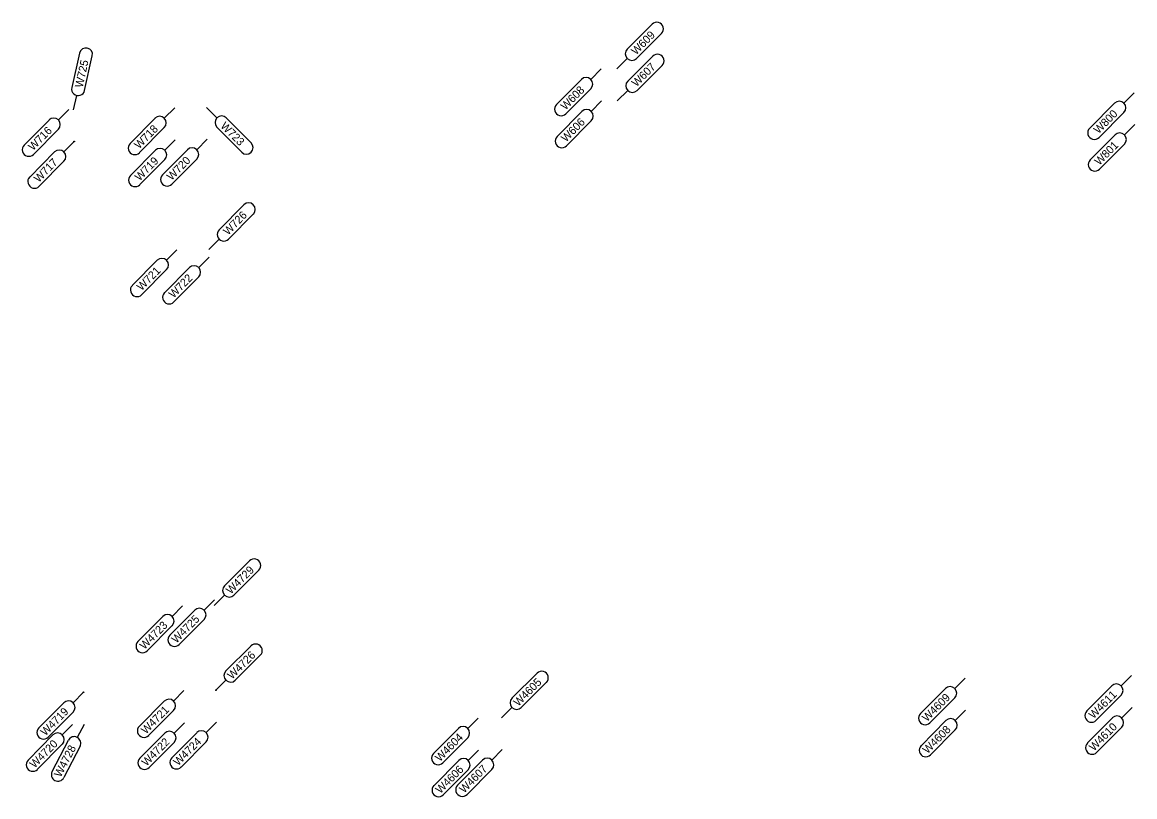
# Model space of a CAD drawing. Extents: x 12479652 to 12487250, y 9842710 to 9846560.
# Drawn here: x 12480939.8 to 12481113.6, y 9842722.3 to 9842843.2 of the extents above; entities that cross this region are included whole.
import ezdxf

# ---------------------------------------------------------------- set-up
doc = ezdxf.new("R2010")
doc.units = 0
doc.layers.add('_CIVIL_CONSTRUCTION', color=7, linetype='Continuous')
doc.layers.add('TextAlignmentLrg', color=7, linetype='Continuous')

msp = doc.modelspace()

# ---------------------------------------------------------------- linework, layer by layer
at = {"layer": '_CIVIL_CONSTRUCTION'}
for p, q in [((12481038.26, 9842842.95), (12481034.35, 9842839.06)), ((12481035.79, 9842837.6), (12481039.71, 9842841.49)), ((12480948.77, 9842838.43), (12480947.57, 9842833.04)), ((12480949.57, 9842832.6), (12480950.77, 9842837.99)), ((12481032.71, 9842835.99), (12481034.34, 9842837.61)), ((12481038.34, 9842837.95), (12481034.43, 9842834.06)), ((12481030.26, 9842835.96), (12481028.64, 9842834.32)), ((12481035.87, 9842832.6), (12481039.79, 9842836.49)), ((12481023.3, 9842830.41), (12481027.19, 9842834.32)), ((12480947.85, 9842829.57), (12480948.35, 9842831.82)), ((12481028.65, 9842832.87), (12481024.76, 9842828.96)), ((12481032.79, 9842830.99), (12481034.42, 9842832.61)), ((12481113.55, 9842832.24), (12481111.93, 9842830.61)), ((12481030.34, 9842830.96), (12481028.72, 9842829.33)), ((12481106.59, 9842826.7), (12481110.48, 9842830.61)), ((12480947.09, 9842829.62), (12480945.47, 9842827.99)), ((12480956.68, 9842824.34), (12480960.57, 9842828.25)), ((12480963.64, 9842829.88), (12480962.02, 9842828.25)), ((12480968.62, 9842829.95), (12480970.25, 9842828.32)), ((12480975.59, 9842824.4), (12480971.7, 9842828.32)), ((12481023.38, 9842825.41), (12481027.27, 9842829.32)), ((12481111.94, 9842829.16), (12481108.05, 9842825.25)), ((12480940.12, 9842824.07), (12480944.01, 9842827.98)), ((12480945.47, 9842826.54), (12480941.58, 9842822.62)), ((12480962.02, 9842826.8), (12480958.13, 9842822.89)), ((12480970.24, 9842826.87), (12480974.13, 9842822.96)), ((12481028.73, 9842827.87), (12481024.84, 9842823.96)), ((12481113.63, 9842827.29), (12481112.01, 9842825.66)), ((12480963.72, 9842824.88), (12480962.1, 9842823.25)), ((12480968.72, 9842824.97), (12480967.1, 9842823.33)), ((12481106.67, 9842821.75), (12481110.56, 9842825.66)), ((12480947.95, 9842824.63), (12480946.33, 9842823)), ((12480956.76, 9842819.34), (12480960.65, 9842823.25)), ((12480961.76, 9842819.42), (12480965.65, 9842823.33)), ((12481112.02, 9842824.21), (12481108.13, 9842820.3)), ((12480940.99, 9842819.08), (12480944.88, 9842823)), ((12480946.34, 9842821.55), (12480942.45, 9842817.64)), ((12480962.1, 9842821.8), (12480958.21, 9842817.89)), ((12480967.1, 9842821.88), (12480963.21, 9842817.97)), ((12480970.58, 9842810.84), (12480974.47, 9842814.76)), ((12480975.93, 9842813.31), (12480972.04, 9842809.4)), ((12480968.97, 9842807.76), (12480970.59, 9842809.39)), ((12480964, 9842807.71), (12480962.37, 9842806.08)), ((12480957.03, 9842802.17), (12480960.92, 9842806.08)), ((12480969.01, 9842806.57), (12480967.39, 9842804.94)), ((12480962.38, 9842804.63), (12480958.49, 9842800.72)), ((12480962.05, 9842801.02), (12480965.94, 9842804.94)), ((12480967.4, 9842803.49), (12480963.51, 9842799.58)), ((12480975.35, 9842759.14), (12480971.44, 9842755.25)), ((12480972.88, 9842753.79), (12480976.8, 9842757.68)), ((12480969.8, 9842752.18), (12480971.43, 9842753.8)), ((12480964.87, 9842752.11), (12480963.25, 9842750.48)), ((12480969.85, 9842753.08), (12480968.23, 9842751.45)), ((12480957.91, 9842746.56), (12480961.8, 9842750.47)), ((12480962.89, 9842747.53), (12480966.78, 9842751.44)), ((12480963.25, 9842749.03), (12480959.36, 9842745.12)), ((12480968.24, 9842750), (12480964.35, 9842746.08)), ((12480975.56, 9842745.85), (12480971.65, 9842741.96)), ((12480973.1, 9842740.51), (12480977.01, 9842744.4)), ((12481020.26, 9842741.61), (12481016.34, 9842737.72)), ((12480970.02, 9842738.89), (12480971.65, 9842740.51)), ((12481017.79, 9842736.27), (12481021.7, 9842740.16)), ((12481087.13, 9842740.84), (12481085.51, 9842739.21)), ((12481106.17, 9842735.71), (12481110.06, 9842739.62)), ((12481113.13, 9842741.26), (12481111.51, 9842739.62)), ((12480949.39, 9842738.62), (12480947.77, 9842736.99)), ((12480965.08, 9842738.88), (12480963.46, 9842737.24)), ((12481080.17, 9842735.29), (12481084.06, 9842739.2)), ((12481111.51, 9842738.17), (12481107.62, 9842734.26)), ((12480942.43, 9842733.08), (12480946.32, 9842736.99)), ((12480958.12, 9842733.33), (12480962.01, 9842737.24)), ((12481014.71, 9842734.65), (12481016.34, 9842736.27)), ((12481085.52, 9842737.76), (12481081.63, 9842733.84)), ((12481113.21, 9842736.26), (12481111.59, 9842734.63)), ((12480947.78, 9842735.54), (12480943.89, 9842731.63)), ((12480963.46, 9842735.79), (12480959.57, 9842731.88)), ((12481011.04, 9842734.61), (12481009.42, 9842732.98)), ((12481087.21, 9842735.84), (12481085.59, 9842734.21)), ((12481106.25, 9842730.71), (12481110.14, 9842734.62)), ((12480947.7, 9842733.6), (12480946.08, 9842731.96)), ((12480949.48, 9842733.62), (12480948.42, 9842731.58)), ((12480965.16, 9842733.88), (12480963.54, 9842732.25)), ((12480970.16, 9842733.96), (12480968.54, 9842732.33)), ((12481004.08, 9842729.07), (12481007.97, 9842732.98)), ((12481080.25, 9842730.29), (12481084.14, 9842734.2)), ((12481085.6, 9842732.76), (12481081.71, 9842728.84)), ((12481111.59, 9842733.17), (12481107.7, 9842729.26)), ((12480940.74, 9842728.05), (12480944.63, 9842731.96)), ((12480944.49, 9842726.25), (12480947.03, 9842731.14)), ((12480958.2, 9842728.33), (12480962.09, 9842732.24)), ((12480963.2, 9842728.41), (12480967.09, 9842732.32)), ((12481009.42, 9842731.53), (12481005.53, 9842727.62)), ((12480946.08, 9842730.51), (12480942.2, 9842726.6)), ((12480948.85, 9842730.2), (12480946.31, 9842725.3)), ((12480963.54, 9842730.79), (12480959.65, 9842726.88)), ((12480968.54, 9842730.87), (12480964.65, 9842726.96)), ((12481011.12, 9842729.61), (12481009.5, 9842727.98)), ((12481014.81, 9842729.67), (12481013.19, 9842728.04)), ((12481004.16, 9842724.07), (12481008.05, 9842727.98)), ((12481007.85, 9842724.13), (12481011.74, 9842728.04)), ((12481009.5, 9842726.53), (12481005.61, 9842722.62)), ((12481013.2, 9842726.59), (12481009.31, 9842722.68))]:
    msp.add_line(p, q, dxfattribs=at)
for centre, start, end in [((12481038.98, 9842842.22), 314.8298, 134.8298), ((12480949.77, 9842838.21), 347.4836, 167.4836), ((12481035.07, 9842838.33), 134.8298, 314.8298), ((12481039.06, 9842837.22), 314.8298, 134.8298), ((12481027.92, 9842833.6), 315.1702, 135.1702), ((12481035.15, 9842833.33), 134.8298, 314.8298), ((12480948.57, 9842832.82), 167.4836, 347.4836), ((12481024.03, 9842829.68), 135.1702, 315.1702), ((12481111.21, 9842829.89), 315.1702, 135.1702), ((12480944.74, 9842827.26), 315.1702, 135.1702), ((12480961.29, 9842827.53), 315.1702, 135.1702), ((12480970.97, 9842827.59), 44.8298, 224.8298), ((12481028, 9842828.6), 315.1702, 135.1702), ((12481107.32, 9842825.97), 135.1702, 315.1702), ((12481024.11, 9842824.68), 135.1702, 315.1702), ((12481111.29, 9842824.94), 315.1702, 135.1702), ((12480940.85, 9842823.35), 135.1702, 315.1702), ((12480945.61, 9842822.27), 315.1702, 135.1702), ((12480957.4, 9842823.61), 135.1702, 315.1702), ((12480961.37, 9842822.53), 315.1702, 135.1702), ((12480966.37, 9842822.61), 315.1702, 135.1702), ((12480974.86, 9842823.68), 224.8298, 44.8298), ((12481107.4, 9842821.02), 135.1702, 315.1702), ((12480941.72, 9842818.36), 135.1702, 315.1702), ((12480957.48, 9842818.61), 135.1702, 315.1702), ((12480962.48, 9842818.69), 135.1702, 315.1702), ((12480975.2, 9842814.03), 315.1702, 135.1702), ((12480971.31, 9842810.12), 135.1702, 315.1702), ((12480961.65, 9842805.35), 315.1702, 135.1702), ((12480966.67, 9842804.21), 315.1702, 135.1702), ((12480957.76, 9842801.44), 135.1702, 315.1702), ((12480962.78, 9842800.3), 135.1702, 315.1702), ((12480976.07, 9842758.41), 314.8298, 134.8298), ((12480972.16, 9842754.52), 134.8298, 314.8298), ((12480967.51, 9842750.72), 315.1702, 135.1702), ((12480962.52, 9842749.75), 315.1702, 135.1702), ((12480958.63, 9842745.84), 135.1702, 315.1702), ((12480963.62, 9842746.81), 135.1702, 315.1702), ((12480976.29, 9842745.13), 314.8298, 134.8298), ((12480972.37, 9842741.24), 134.8298, 314.8298), ((12481020.98, 9842740.88), 314.8298, 134.8298), ((12481110.78, 9842738.9), 315.1702, 135.1702), ((12481084.79, 9842738.48), 315.1702, 135.1702), ((12480947.05, 9842736.26), 315.1702, 135.1702), ((12480962.74, 9842736.52), 315.1702, 135.1702), ((12481017.07, 9842736.99), 134.8298, 314.8298), ((12481080.9, 9842734.57), 135.1702, 315.1702), ((12481084.87, 9842733.48), 315.1702, 135.1702), ((12481106.89, 9842734.98), 135.1702, 315.1702), ((12481110.86, 9842733.9), 315.1702, 135.1702), ((12480943.16, 9842732.35), 135.1702, 315.1702), ((12480958.85, 9842732.6), 135.1702, 315.1702), ((12481008.69, 9842732.26), 315.1702, 135.1702), ((12480945.36, 9842731.24), 315.1702, 135.1702), ((12480947.94, 9842730.67), 332.5319, 152.5319), ((12480962.82, 9842731.52), 315.1702, 135.1702), ((12480967.82, 9842731.6), 315.1702, 135.1702), ((12481080.98, 9842729.57), 135.1702, 315.1702), ((12481106.97, 9842729.98), 135.1702, 315.1702), ((12480941.47, 9842727.32), 135.1702, 315.1702), ((12480958.93, 9842727.61), 135.1702, 315.1702), ((12480963.93, 9842727.69), 135.1702, 315.1702), ((12481004.8, 9842728.34), 135.1702, 315.1702), ((12481008.77, 9842727.26), 315.1702, 135.1702), ((12481012.47, 9842727.32), 315.1702, 135.1702), ((12480945.4, 9842725.78), 152.5319, 332.5319), ((12481004.88, 9842723.34), 135.1702, 315.1702), ((12481008.58, 9842723.4), 135.1702, 315.1702)]:
    msp.add_arc(centre, 1.03, start, end, dxfattribs=at)
at = {"layer": 'TextAlignmentLrg'}
for centre in [(12480947.94, 9842824.62), (12480949.4, 9842738.63), (12480970.09, 9842738.96)]:
    msp.add_circle(centre, 0.05, dxfattribs=at)

# ---------------------------------------------------------------- texts
at = {"layer": '_CIVIL_CONSTRUCTION'}
for s, rotation, p in [('W609', 44.8298, (12481035.7, 9842838.06)), ('W725', 77.4836, (12480949.25, 9842832.95)), ('W607', 44.8298, (12481035.79, 9842833.07)), ('W608', 45.1702, (12481024.69, 9842829.45)), ('W606', 45.1702, (12481024.77, 9842824.45)), ('W800', 45.1702, (12481107.98, 9842825.74)), ('W716', 45.1702, (12480941.51, 9842823.11)), ('W718', 45.1702, (12480958.07, 9842823.38)), ('W723', 314.8298, (12480970.71, 9842826.95)), ('W801', 45.1702, (12481108.1, 9842820.82)), ('W717', 45.1702, (12480942.39, 9842818.14)), ('W719', 45.1702, (12480958.15, 9842818.38)), ('W720', 45.1702, (12480963.15, 9842818.46)), ('W726', 45.1702, (12480971.97, 9842809.91)), ('W721', 45.1702, (12480958.46, 9842801.24)), ('W722', 45.1702, (12480963.46, 9842800.09)), ('W4729', 44.8298, (12480972.4, 9842753.86)), ('W4725', 45.1702, (12480963.9, 9842746.19)), ('W4723', 45.1702, (12480958.91, 9842745.22)), ('W4726', 44.8298, (12480972.61, 9842740.57)), ('W4605', 44.8298, (12481017.32, 9842736.35)), ('W4609', 45.1702, (12481081.17, 9842733.94)), ('W4611', 45.1702, (12481107.2, 9842734.39)), ('W4719', 45.1702, (12480943.43, 9842731.73)), ('W4721', 45.1702, (12480959.15, 9842732.01)), ('W4608', 45.1702, (12481081.25, 9842728.94)), ('W4610', 45.1702, (12481107.25, 9842729.36)), ('W4720', 45.1702, (12480941.74, 9842726.7)), ('W4722', 45.1702, (12480959.22, 9842727)), ('W4724', 45.1702, (12480964.19, 9842727.05)), ('W4604', 45.1702, (12481005.07, 9842727.71)), ('W4728', 62.5319, (12480945.84, 9842725.26)), ('W4606', 45.1702, (12481005.15, 9842722.71)), ('W4607', 45.1702, (12481008.86, 9842722.79))]:
    msp.add_text(s, height=1.25, rotation=rotation, dxfattribs=at).set_placement(p)

doc.saveas('drawing.dxf')
